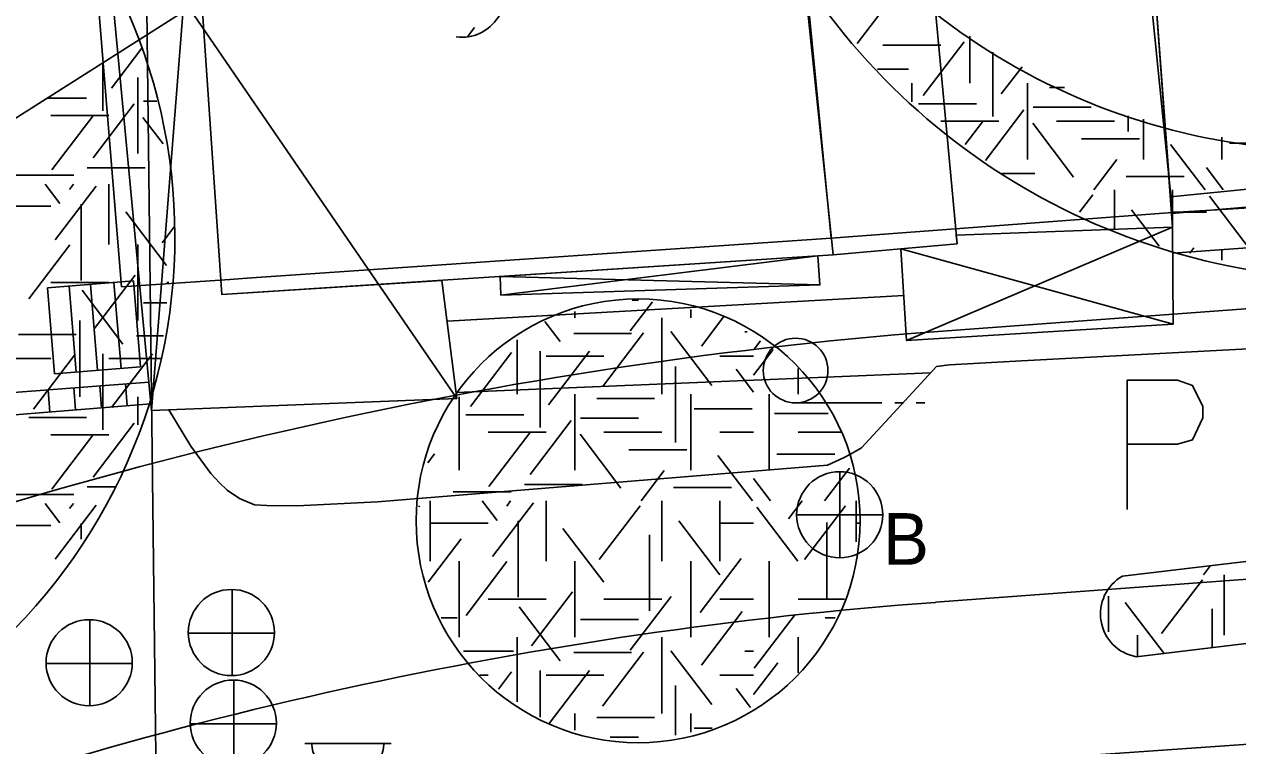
# Model space of a CAD drawing. Extents: x 419101 to 420177, y 4451541 to 4452254.
# Drawn here: x 419848.32 to 419876.47, y 4451832.16 to 4451848.9 of the extents above; entities that cross this region are included whole.
import ezdxf

# ---------------------------------------------------------------- set-up
doc = ezdxf.new("R2010")
doc.units = 0
for name, color, linetype in [('2_KADASTRO', 7, 'Continuous'), ('3_HALİHAZIR', 7, 'Continuous'), ('Level 10', 7, 'Continuous'), ('Level 41', 7, 'Continuous'), ('Level 60', 7, 'Continuous'), ('Level 62', 7, 'Continuous')]:
    doc.layers.add(name, color=color, linetype=linetype)

msp = doc.modelspace()

# ---------------------------------------------------------------- linework, layer by layer
at = {"layer": '2_KADASTRO'}
for points in [[(419849.678, 4451853.779), (419850.205, 4451863.636), (419851.856, 4451863.604), (419858.298, 4451863.477), (419863.175, 4451863.381), (419865.171, 4451863.342), (419865.941, 4451855.203), (419867.038, 4451843.936), (419853.486, 4451843.011), (419853.286, 4451842.996), (419853.086, 4451842.982), (419850.576, 4451842.812)], [(419865.171, 4451863.342), (419871.156, 4451863.224), (419873.139, 4451863.185), (419874.14, 4451852.682), (419874.959, 4451844.532), (419867.038, 4451843.936), (419865.941, 4451855.203)], [(419873.139, 4451863.185), (419873.151, 4451863.185), (419879.138, 4451863.068), (419880.978, 4451863.032), (419882.988, 4451845.025), (419874.959, 4451844.532), (419874.14, 4451852.682)]]:
    msp.add_lwpolyline(points, close=True, dxfattribs=at)
at = {"layer": '3_HALİHAZIR'}
for p, q in [((419850.113, 4451852.249), (419858.356, 4451840.219)), ((419852.243, 4451852.253), (419851.27, 4451839.938)), ((419874.957, 4451844.192), (419868.782, 4451841.567)), ((419868.654, 4451843.693), (419874.973, 4451841.944)), ((419859.372, 4451842.62), (419866.731, 4451843.528)), ((419859.36, 4451843.049), (419866.777, 4451842.854)), ((419850.852, 4451842.949), (419848.859, 4451842.784)), ((419850.852, 4451842.949), (419848.859, 4451842.784)), ((419848.859, 4451842.784), (419849.024, 4451840.791)), ((419848.859, 4451842.784), (419849.024, 4451840.791)), ((419849.527, 4451840.832), (419849.362, 4451842.826)), ((419850.02, 4451840.873), (419849.856, 4451842.866)), ((419850.566, 4451840.918), (419850.401, 4451842.912)), ((419851.017, 4451840.956), (419850.852, 4451842.949)), ((419851.017, 4451840.956), (419850.852, 4451842.949)), ((419849.024, 4451840.791), (419851.017, 4451840.956)), ((419849.024, 4451840.791), (419851.017, 4451840.956)), ((419850.069, 4451840.511), (419850.109, 4451840)), ((419850.668, 4451840.557), (419850.707, 4451840.048)), ((419848.873, 4451840.419), (419848.912, 4451839.903)), ((419849.471, 4451840.465), (419849.511, 4451839.952)), ((419866.213, 4451840.118), (419868.213, 4451840.118)), ((419868.513, 4451840.118), (419868.713, 4451840.118)), ((419869.013, 4451840.118), (419869.213, 4451840.118)), ((419867.237, 4451838.52), (419867.237, 4451836.52)), ((419866.237, 4451837.52), (419868.237, 4451837.52)), ((419853.14, 4451833.779), (419853.14, 4451835.779)), ((419849.842, 4451833.077), (419849.842, 4451835.077)), ((419852.12, 4451834.769), (419854.12, 4451834.769)), ((419848.822, 4451834.067), (419850.822, 4451834.067)), ((419853.184, 4451831.675), (419853.184, 4451833.675)), ((419852.164, 4451832.665), (419854.164, 4451832.665)), ((419854.828, 4451832.209), (419856.828, 4451832.209))]:
    msp.add_line(p, q, dxfattribs=at)
for points in [[(419852.905, 4451842.63), (419852.381, 4451850.22), (419851.398, 4451864.63), (419851.896, 4451864.66), (419859.061, 4451864.468), (419859.635, 4451855.634), (419862.462, 4451855.808), (419862.531, 4451854.538), (419865.905, 4451854.763), (419866.152, 4451852.531), (419867.082, 4451843.551)], [(419878.62, 4451859.319), (419881.249, 4451859.272), (419881.302, 4451857.003), (419881.725, 4451857.087), (419882.986, 4451845.7), (419883.049, 4451845.203), (419874.934, 4451844.514), (419874.906, 4451844.897), (419874.448, 4451851.135), (419873.961, 4451855.232), (419873.131, 4451863.848), (419878.124, 4451863.904)], [(419874.906, 4451844.897), (419874.448, 4451851.135), (419873.961, 4451855.232), (419877.869, 4451855.633), (419877.772, 4451856.859), (419878.216, 4451856.877), (419878.181, 4451859.327), (419881.249, 4451859.272), (419881.302, 4451857.003), (419881.725, 4451857.087), (419882.986, 4451845.7)], [(419874.957, 4451844.192), (419869.941, 4451844.008), (419869.96, 4451843.811), (419867.082, 4451843.551), (419866.152, 4451852.531), (419869.126, 4451852.787), (419869.057, 4451853.229), (419871.822, 4451853.597), (419872.077, 4451852.917), (419872.43, 4451852.776), (419872.887, 4451852.905), (419872.904, 4451853.175), (419873.84, 4451853.395), (419874.448, 4451851.135)], [(419867.082, 4451843.551), (419866.152, 4451852.531), (419869.126, 4451852.787), (419869.96, 4451843.811)], [(419858.007, 4451842.961), (419852.905, 4451842.63), (419852.381, 4451850.22), (419852.243, 4451852.253), (419850.113, 4451852.249), (419851.27, 4451839.938), (419858.356, 4451840.219)], [(419868.654, 4451843.693), (419869.96, 4451843.811), (419869.941, 4451844.008), (419874.957, 4451844.192), (419874.973, 4451841.944), (419868.782, 4451841.567)], [(419859.372, 4451842.62), (419859.36, 4451843.049), (419866.731, 4451843.528), (419866.777, 4451842.854)], [(419840.539, 4451839.23), (419840.498, 4451839.777), (419851.208, 4451840.598), (419851.255, 4451840.092)]]:
    msp.add_lwpolyline(points, close=True, dxfattribs=at)
for points in [[(419937.395, 4451848.633), (419935.359, 4451848.355), (419923.109, 4451847.141), (419907.272, 4451845.896), (419874.962, 4451843.594)], [(419938.929, 4451846.961), (419937.809, 4451846.46), (419936.95, 4451846.037), (419936.021, 4451845.735), (419934.96, 4451845.523), (419913.204, 4451843.465), (419903.423, 4451842.784), (419871.452, 4451841.095), (419869.78, 4451840.999), (419869.483, 4451840.96), (419867.739, 4451839.072), (419867.489, 4451838.923), (419867.321, 4451838.841), (419866.952, 4451838.669), (419856.516, 4451837.82), (419854.654, 4451837.724), (419853.949, 4451837.732), (419853.658, 4451837.754), (419853.311, 4451837.896), (419853.023, 4451838.088), (419852.852, 4451838.26), (419852.65, 4451838.481), (419852.183, 4451839.113), (419851.674, 4451839.954)], [(419868.72, 4451842.61), (419858.128, 4451842.016)], [(419858.339, 4451840.355), (419869.346, 4451840.812)], [(419873.901, 4451840.642), (419875.071, 4451840.642)], [(419873.901, 4451837.642), (419873.901, 4451840.642)], [(419875.071, 4451840.642), (419875.421, 4451840.522), (419875.661, 4451840.032), (419875.661, 4451839.772), (419875.421, 4451839.262), (419875.071, 4451839.162)], [(419875.071, 4451839.162), (419873.901, 4451839.162)], [(419884.316, 4451832.013), (419884.164, 4451832.208), (419884.092, 4451832.268), (419883.978, 4451832.362), (419883.73, 4451832.495), (419883.249, 4451832.652), (419868.981, 4451831.651)]]:
    msp.add_lwpolyline(points, dxfattribs=at)
for centre, radius in [((419866.213, 4451840.868), 0.75), ((419867.237, 4451837.52), 1), ((419853.125, 4451834.787), 1), ((419849.826, 4451834.085), 1), ((419853.168, 4451832.683), 1)]:
    msp.add_circle(centre, radius, dxfattribs=at)
msp.add_arc((419855.828, 4451832.239), 0.837, 183.298, 356.9072, dxfattribs=at)
at = {"layer": 'Level 10'}
msp.add_lwpolyline([(419958.201, 4451879.006), (419966.53, 4451769.671), (419931.06, 4451766.859), (419938.096, 4451697.79), (419879.097, 4451703.767), (419870.357, 4451698.446), (419851.433, 4451826.814), (419850.731, 4451885.176)], dxfattribs=at)
at = {"layer": 'Level 41'}
for p, q in [((419867.641, 4451848.456), (419868.446, 4451849.516)), ((419858.593, 4451848.603), (419858.766, 4451848.831)), ((419868.238, 4451848.42), (419869.581, 4451848.42)), ((419869.174, 4451847.25), (419870.124, 4451848.5)), ((419870.253, 4451848.626), (419870.253, 4451847.537)), ((419850.343, 4451847.419), (419851.049, 4451848.349)), ((419870.785, 4451848.253), (419870.785, 4451846.764)), ((419850.143, 4451848.013), (419850.143, 4451846.897)), ((419868.115, 4451847.86), (419868.835, 4451847.86)), ((419870.985, 4451847.286), (419871.466, 4451847.92)), ((419849.611, 4451847.675), (419849.611, 4451847.67)), ((419850.954, 4451845.902), (419850.954, 4451847.67)), ((419868.91, 4451847.104), (419868.91, 4451847.537)), ((419871.596, 4451845.769), (419871.596, 4451847.537)), ((419872.101, 4451847.439), (419872.45, 4451847.439)), ((419848.845, 4451847.187), (419849.765, 4451847.187)), ((419849.918, 4451845.805), (419850.867, 4451847.055)), ((419851.085, 4451847.116), (419851.393, 4451847.116)), ((419869.064, 4451847.054), (419870.407, 4451847.054)), ((419871.727, 4451846.983), (419873.07, 4451846.983)), ((419848.939, 4451846.786), (419850.282, 4451846.786)), ((419848.958, 4451845.526), (419849.907, 4451846.775)), ((419851.538, 4451846.126), (419851.071, 4451846.74)), ((419870.616, 4451845.746), (419871.509, 4451846.922)), ((419873.928, 4451846.779), (419873.928, 4451846.414)), ((419874.282, 4451845.769), (419874.282, 4451846.698)), ((419869.581, 4451846.653), (419870.924, 4451846.653)), ((419870.15, 4451846.117), (419870.549, 4451846.642)), ((419872.663, 4451845.358), (419871.713, 4451846.607)), ((419872.267, 4451846.653), (419873.61, 4451846.653)), ((419872.846, 4451846.246), (419874.189, 4451846.246)), ((419876.103, 4451845.769), (419876.103, 4451846.282)), ((419876.28, 4451846.142), (419876.714, 4451846.142)), ((419875.712, 4451845.06), (419874.91, 4451846.116)), ((419849.781, 4451845.574), (419851.124, 4451845.574)), ((419873.129, 4451845.06), (419873.666, 4451845.766)), ((419876.135, 4451845.06), (419875.741, 4451845.578)), ((419848.129, 4451845.399), (419849.472, 4451845.399)), ((419870.999, 4451845.441), (419871.766, 4451845.441)), ((419873.885, 4451845.372), (419875.228, 4451845.372)), ((419849.145, 4451844.741), (419848.801, 4451845.193)), ((419849.038, 4451843.899), (419849.988, 4451845.149)), ((419849.371, 4451845.073), (419849.462, 4451845.193)), ((419850.282, 4451845.193), (419850.282, 4451843.795)), ((419873.61, 4451845.06), (419873.61, 4451844.154)), ((419874.953, 4451845.06), (419874.953, 4451843.685)), ((419874.953, 4451845.06), (419874.953, 4451843.685)), ((419849.638, 4451844.726), (419849.638, 4451842.959)), ((419872.799, 4451844.542), (419873.106, 4451844.947)), ((419876.762, 4451843.662), (419875.813, 4451844.912)), ((419847.596, 4451844.679), (419848.939, 4451844.679)), ((419851.622, 4451843.304), (419850.673, 4451844.553)), ((419874.644, 4451843.755), (419874.005, 4451844.595)), ((419874.953, 4451844.546), (419875.741, 4451844.546)), ((419851.515, 4451843.83), (419851.805, 4451844.211)), ((419848.427, 4451842.533), (419849.376, 4451843.783)), ((419850.954, 4451843.795), (419850.954, 4451842.028)), ((419875.357, 4451843.595), (419875.451, 4451843.719)), ((419876.103, 4451843.427), (419876.103, 4451843.662)), ((419849.944, 4451841.832), (419850.895, 4451843.081)), ((419848.939, 4451842.911), (419850.282, 4451842.911)), ((419851.625, 4451842.911), (419851.673, 4451842.911)), ((419850.61, 4451841.482), (419849.66, 4451842.731)), ((419862.376, 4451841.786), (419862.89, 4451842.463)), ((419862.425, 4451842.5), (419862.569, 4451842.5)), ((419851.085, 4451842.441), (419851.626, 4451842.441)), ((419861.095, 4451842.238), (419861.095, 4451842.087)), ((419863.781, 4451842.285), (419863.781, 4451842.087)), ((419863.781, 4451842.285), (419863.781, 4451842.087)), ((419849.611, 4451842.028), (419849.611, 4451840.261)), ((419860.751, 4451841.541), (419860.397, 4451842.006)), ((419863.109, 4451842.087), (419863.109, 4451840.32)), ((419864.027, 4451841.435), (419864.551, 4451842.124)), ((419848.183, 4451841.704), (419849.526, 4451841.704)), ((419850.925, 4451841.671), (419851.548, 4451841.671)), ((419861.066, 4451841.73), (419862.409, 4451841.73)), ((419861.736, 4451840.489), (419862.686, 4451841.739)), ((419864.266, 4451840.523), (419863.317, 4451841.772)), ((419865.036, 4451841.763), (419865.09, 4451841.763)), ((419859.752, 4451841.577), (419859.752, 4451840.32)), ((419865.24, 4451840.757), (419865.696, 4451841.357)), ((419865.25, 4451841.366), (419865.396, 4451841.558)), ((419847.596, 4451841.144), (419848.939, 4451841.144)), ((419848.532, 4451839.974), (419849.482, 4451841.224)), ((419850.143, 4451841.256), (419850.143, 4451839.488)), ((419850.282, 4451841.144), (419851.495, 4451841.144)), ((419850.343, 4451840.01), (419851.292, 4451841.259)), ((419858.673, 4451840.033), (419859.623, 4451841.283)), ((419860.284, 4451841.315), (419860.284, 4451839.547)), ((419860.423, 4451841.203), (419861.766, 4451841.203)), ((419860.484, 4451840.069), (419861.433, 4451841.318)), ((419864.452, 4451841.203), (419865.24, 4451841.203)), ((419863.427, 4451840.965), (419863.427, 4451839.197)), ((419865.24, 4451840.363), (419864.834, 4451840.897)), ((419866.273, 4451840.914), (419866.273, 4451840.32)), ((419850.954, 4451839.611), (419850.954, 4451840.261)), ((419858.409, 4451838.552), (419858.409, 4451840.258)), ((419861.095, 4451838.552), (419861.095, 4451840.32)), ((419861.6, 4451840.222), (419862.943, 4451840.222)), ((419863.781, 4451838.552), (419863.781, 4451840.32)), ((419865.602, 4451838.552), (419865.602, 4451840.32)), ((419863.863, 4451839.977), (419865.206, 4451839.977)), ((419848.422, 4451839.778), (419849.765, 4451839.778)), ((419849.918, 4451838.396), (419850.867, 4451839.646)), ((419858.563, 4451839.837), (419859.906, 4451839.837)), ((419860.059, 4451838.455), (419861.008, 4451839.705)), ((419861.226, 4451839.766), (419862.569, 4451839.766)), ((419865.725, 4451839.871), (419866.969, 4451839.871)), ((419848.939, 4451839.377), (419850.282, 4451839.377)), ((419848.958, 4451838.117), (419849.907, 4451839.366)), ((419859.08, 4451839.436), (419860.423, 4451839.436)), ((419859.099, 4451838.176), (419860.048, 4451839.425)), ((419862.162, 4451838.141), (419861.212, 4451839.39)), ((419861.766, 4451839.436), (419863.109, 4451839.436)), ((419864.452, 4451839.436), (419865.24, 4451839.436)), ((419866.273, 4451839.436), (419867.26, 4451839.436)), ((419857.679, 4451838.726), (419857.837, 4451838.934)), ((419862.345, 4451839.029), (419863.688, 4451839.029)), ((419865.211, 4451837.843), (419864.409, 4451838.899)), ((419865.779, 4451838.925), (419867.121, 4451838.925)), ((419862.628, 4451837.843), (419863.165, 4451838.549)), ((419866.887, 4451837.843), (419867.466, 4451838.605)), ((419865.634, 4451837.843), (419865.24, 4451838.361)), ((419848.129, 4451837.99), (419849.472, 4451837.99)), ((419849.781, 4451838.165), (419850.43, 4451838.165)), ((419858.27, 4451838.049), (419859.613, 4451838.049)), ((419859.922, 4451838.224), (419861.265, 4451838.224)), ((419863.384, 4451838.155), (419864.727, 4451838.155)), ((419849.145, 4451837.332), (419848.801, 4451837.784)), ((419849.038, 4451836.49), (419849.988, 4451837.74)), ((419849.371, 4451837.664), (419849.462, 4451837.784)), ((419857.473, 4451837.707), (419857.491, 4451837.73)), ((419857.737, 4451837.843), (419857.737, 4451836.445)), ((419859.286, 4451837.391), (419858.942, 4451837.843)), ((419859.179, 4451836.549), (419860.129, 4451837.799)), ((419859.512, 4451837.723), (419859.603, 4451837.843)), ((419860.423, 4451837.843), (419860.423, 4451836.445)), ((419861.656, 4451836.48), (419862.605, 4451837.73)), ((419863.109, 4451837.843), (419863.109, 4451836.445)), ((419864.452, 4451837.843), (419864.452, 4451836.445)), ((419864.452, 4451837.843), (419864.452, 4451836.445)), ((419866.261, 4451836.445), (419865.312, 4451837.695)), ((419866.05, 4451837.426), (419866.367, 4451837.843)), ((419866.421, 4451836.48), (419867.37, 4451837.73)), ((419867.616, 4451837.843), (419867.616, 4451836.892)), ((419847.596, 4451837.27), (419848.939, 4451837.27)), ((419849.638, 4451837.317), (419849.638, 4451836.954)), ((419857.737, 4451837.329), (419859.08, 4451837.329)), ((419859.779, 4451837.376), (419859.779, 4451835.609)), ((419861.763, 4451835.954), (419860.814, 4451837.203)), ((419864.453, 4451836.129), (419863.504, 4451837.378)), ((419864.452, 4451837.329), (419865.24, 4451837.329)), ((419866.941, 4451837.341), (419866.941, 4451835.574)), ((419867.616, 4451837.329), (419867.705, 4451837.329)), ((419857.691, 4451835.957), (419858.451, 4451836.958)), ((419862.827, 4451837.055), (419862.827, 4451835.288)), ((419858.409, 4451836.445), (419858.409, 4451834.678)), ((419858.568, 4451835.183), (419859.517, 4451836.433)), ((419861.095, 4451836.445), (419861.095, 4451834.678)), ((419863.781, 4451836.445), (419863.781, 4451834.678)), ((419863.781, 4451836.445), (419863.781, 4451834.678)), ((419864.001, 4451835.252), (419864.95, 4451836.502)), ((419865.602, 4451834.678), (419865.602, 4451836.445)), ((419875.675, 4451836.126), (419875.838, 4451836.34)), ((419874.703, 4451834.763), (419875.652, 4451836.013)), ((419876.156, 4451836.126), (419876.156, 4451834.728)), ((419860.085, 4451834.482), (419861.036, 4451835.731)), ((419859.08, 4451835.561), (419860.423, 4451835.561)), ((419861.766, 4451835.561), (419863.109, 4451835.561)), ((419862.376, 4451834.377), (419863.325, 4451835.627)), ((419864.452, 4451835.561), (419865.24, 4451835.561)), ((419866.273, 4451835.561), (419867.344, 4451835.561)), ((419873.47, 4451835.628), (419873.47, 4451834.805)), ((419874.759, 4451834.304), (419873.861, 4451835.486)), ((419860.751, 4451834.132), (419859.801, 4451835.381)), ((419864.027, 4451834.026), (419864.977, 4451835.275)), ((419865.25, 4451833.957), (419866.199, 4451835.206)), ((419875.874, 4451835.338), (419875.874, 4451834.438)), ((419857.992, 4451835.127), (419858.361, 4451835.127)), ((419861.226, 4451835.091), (419862.569, 4451835.091)), ((419866.897, 4451835.127), (419867.134, 4451835.127)), ((419859.752, 4451834.678), (419859.752, 4451833.181)), ((419863.109, 4451834.678), (419863.109, 4451832.911)), ((419866.273, 4451834.678), (419866.273, 4451833.852)), ((419874.142, 4451834.728), (419874.142, 4451834.229)), ((419858.506, 4451834.354), (419859.667, 4451834.354)), ((419861.066, 4451834.321), (419862.409, 4451834.321)), ((419861.736, 4451833.08), (419862.686, 4451834.33)), ((419864.266, 4451833.114), (419863.317, 4451834.363)), ((419865.036, 4451834.354), (419865.24, 4451834.354)), ((419865.24, 4451833.348), (419865.799, 4451834.084)), ((419858.877, 4451833.794), (419859.08, 4451833.794)), ((419859.318, 4451833.473), (419859.623, 4451833.874)), ((419860.284, 4451833.906), (419860.284, 4451832.823)), ((419860.423, 4451833.794), (419861.766, 4451833.794)), ((419860.498, 4451832.679), (419861.433, 4451833.909)), ((419864.452, 4451833.794), (419865.24, 4451833.794)), ((419863.427, 4451833.556), (419863.427, 4451832.403)), ((419865.168, 4451833.049), (419864.834, 4451833.488)), ((419861.095, 4451832.523), (419861.095, 4451832.911)), ((419863.781, 4451832.472), (419863.781, 4451832.911)), ((419861.6, 4451832.813), (419862.943, 4451832.813)), ((419861.914, 4451832.357), (419862.569, 4451832.357)), ((419863.863, 4451832.568), (419864.276, 4451832.568))]:
    msp.add_line(p, q, dxfattribs=at)
at = {"layer": 'Level 60'}
for points in [[(419888.292, 4451843.159), (419868.997, 4451841.736)], [(419925.269, 4451839.604), (419869.458, 4451835.488)]]:
    msp.add_lwpolyline(points, dxfattribs=at)
for centre, radius, start, end in [((419877.418, 4451739.094), 102.987, 94.68984, 112.30253), ((419876.549, 4451739.049), 96.699, 94.2053, 110.62966)]:
    msp.add_arc(centre, radius, start, end, dxfattribs=at)
at = {"layer": 'Level 62'}
for p, q in [((419842.761, 4451843.317), (419863.675, 4451856.621)), ((419873.797, 4451836.095), (419883.026, 4451837.204)), ((419874.113, 4451834.226), (419883.251, 4451835.324))]:
    msp.add_line(p, q, dxfattribs=at)
for centre, radius, start, end in [((419878.686, 4451860.977), 15, 212.4983, 276.8555), ((419838.814, 4451843.978), 13, 290.1603, 31.867), ((419858.468, 4451849.602), 1, 262.7319, 32.2828), ((419879.342, 4451858.485), 15.5, 212.0555, 276.8532), ((419874.291, 4451835.217), 1.007, 119.4167, 259.7924)]:
    msp.add_arc(centre, radius, start, end, dxfattribs=at)
msp.add_ellipse((419862.56, 4451837.379), major_axis=(5.15, 0), ratio=0.999806, dxfattribs=at)

# ---------------------------------------------------------------- texts
at = {"layer": '3_HALİHAZIR'}
msp.add_text('B', height=1.2, dxfattribs=at).set_placement((419868.237, 4451836.359))

doc.saveas('drawing.dxf')
